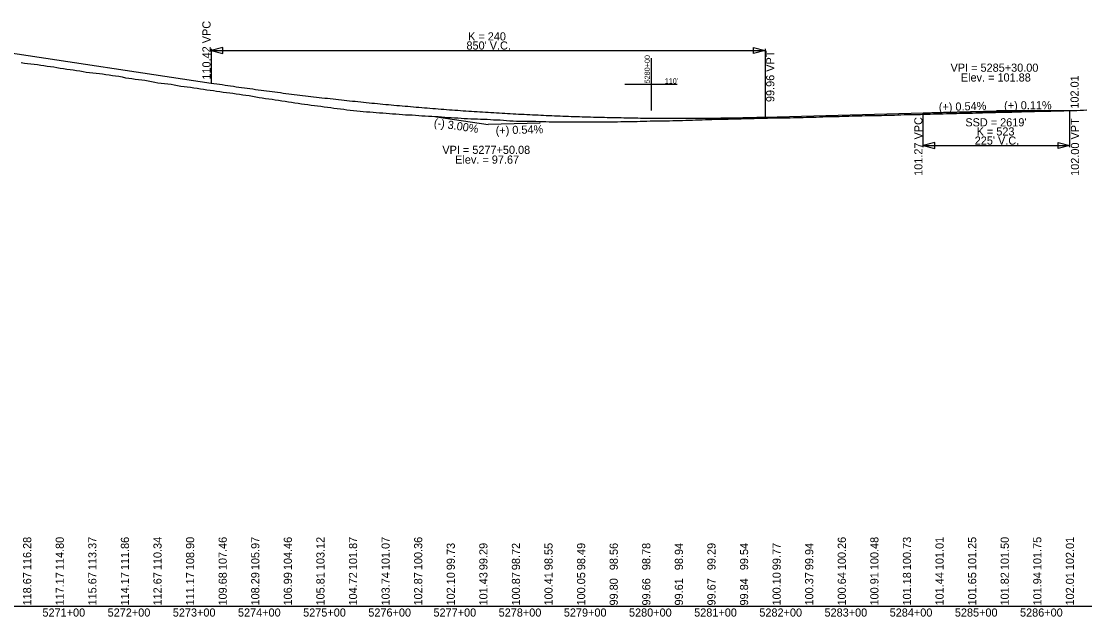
# Model space of a CAD drawing. Extents: x 2147288 to 2220488, y 740833 to 759333.
# Drawn here: x 2159415 to 2161047, y 742067 to 742980 of the extents above; entities that cross this region are included whole.
import ezdxf

# ---------------------------------------------------------------- set-up
doc = ezdxf.new("R2010")
doc.units = 0
for name, color, linetype in [('RD_DDB_GradeTX', 7, 'Continuous'), ('RD_DDB_Profile_EX', 7, 'Continuous'), ('RD_DDB_Profile_Lbl', 7, 'Continuous'), ('RD_DDB_Profile_PR', 7, 'Continuous'), ('RD_DDB_StaTX', 7, 'Continuous'), ('RD_DDB_StripGrade', 7, 'Continuous'), ('RD_DDB_VCLbl', 7, 'Continuous'), ('RD_GPK_Profile_Cell', 7, 'Continuous')]:
    doc.layers.add(name, color=color, linetype=linetype)

msp = doc.modelspace()

# ---------------------------------------------------------------- linework, layer by layer
at = {"layer": 'RD_DDB_GradeTX'}
for p, q in [((2160052, 742833.6), (2160131.2, 742821.8)), ((2160831.1, 742840.7), (2160911.1, 742842.8)), ((2160991.1, 742843.3), (2160911.1, 742842.8)), ((2160211.1, 742823.9), (2160131.2, 742821.8))]:
    msp.add_line(p, q, dxfattribs=at)
at = {"layer": 'RD_DDB_Profile_EX'}
for points in [[(2159414.6, 742916.9), (2159419.6, 742916.2), (2159424.6, 742915.5), (2159429.6, 742915), (2159434.6, 742914.4), (2159439.6, 742913.7), (2159444.6, 742913), (2159449.6, 742912.2), (2159454.6, 742911.4), (2159459.6, 742911), (2159464.6, 742910.2), (2159469.6, 742909.4), (2159474.6, 742908.4), (2159479.6, 742907.6), (2159484.6, 742907), (2159489.6, 742906.3), (2159494.6, 742905.5), (2159499.6, 742904.7), (2159504.6, 742904), (2159509.6, 742903.1), (2159514.6, 742902.1), (2159519.6, 742901.6), (2159524.6, 742901.1), (2159529.6, 742900.5), (2159534.6, 742899.9)], [(2159534.6, 742899.9), (2159539.6, 742899.4), (2159544.6, 742898.7), (2159549.6, 742897.9), (2159554.6, 742897.1), (2159559.6, 742896.6), (2159564.6, 742895.8), (2159569.6, 742894.8), (2159574.6, 742893.7), (2159579.6, 742892.9), (2159584.6, 742892.2), (2159589.6, 742891.5), (2159594.6, 742890.9), (2159599.6, 742890.6), (2159604.6, 742889.9), (2159609.6, 742889), (2159614.6, 742888), (2159619.6, 742887), (2159624.6, 742885.9), (2159629.6, 742885.3), (2159634.6, 742884.8), (2159639.6, 742884.2), (2159644.6, 742883.5), (2159649.6, 742882.7), (2159654.6, 742881.8), (2159659.6, 742880.8), (2159664.6, 742880.4), (2159669.6, 742879.9), (2159674.6, 742879.1), (2159679.6, 742878.1), (2159684.6, 742877.4), (2159689.6, 742876.7), (2159694.6, 742876), (2159699.6, 742875.3), (2159704.6, 742874.6), (2159709.6, 742873.8), (2159714.6, 742873.2), (2159719.6, 742872.5), (2159724.6, 742871.5), (2159729.6, 742870.9), (2159734.6, 742870.4), (2159739.6, 742869.8), (2159744.6, 742869), (2159749.6, 742868.2), (2159754.6, 742867.4), (2159759.6, 742867), (2159764.6, 742866.2), (2159769.6, 742865.2), (2159774.6, 742864.3), (2159779.6, 742863.5), (2159784.6, 742862.7), (2159789.6, 742861.9), (2159794.6, 742861.2), (2159799.6, 742860.5), (2159804.6, 742859.9), (2159809.6, 742859.1), (2159814.6, 742858.3), (2159819.6, 742857.5), (2159824.6, 742856.7), (2159829.6, 742856), (2159834.6, 742855.2), (2159839.6, 742854.5), (2159844.6, 742853.8), (2159849.6, 742853.1), (2159854.6, 742852.4), (2159859.6, 742851.7), (2159864.6, 742851.1), (2159869.6, 742850.6), (2159874.6, 742850), (2159879.6, 742849.2), (2159884.6, 742848.5), (2159889.6, 742847.8), (2159894.6, 742847.1), (2159899.6, 742846.5), (2159904.6, 742845.8), (2159909.6, 742845.2), (2159914.6, 742844.6), (2159919.6, 742844.1), (2159924.6, 742843.5), (2159929.6, 742842.9), (2159934.6, 742842.4), (2159939.6, 742841.9), (2159944.6, 742841.4), (2159949.6, 742841.1), (2159954.6, 742840.8), (2159959.6, 742840.4), (2159964.6, 742840), (2159969.6, 742839.6), (2159974.6, 742839.3), (2159979.6, 742838.9), (2159984.6, 742838.4), (2159989.6, 742838.1), (2159994.6, 742837.7), (2159999.6, 742837.2), (2160004.6, 742836.9), (2160009.6, 742836.7), (2160014.6, 742836.5), (2160019.6, 742836.1), (2160024.6, 742835.7), (2160029.6, 742835.4), (2160034.6, 742835)], [(2160534.6, 742831.2), (2160539.6, 742831.3), (2160544.6, 742831.4), (2160549.6, 742831.5), (2160554.6, 742831.6), (2160559.6, 742831.7), (2160564.6, 742831.9), (2160569.6, 742832.1), (2160574.6, 742832.2), (2160579.6, 742832.3), (2160584.6, 742832.3), (2160589.6, 742832.3), (2160594.6, 742832.3), (2160599.6, 742832.5), (2160604.6, 742832.6), (2160609.6, 742832.7), (2160614.6, 742832.8), (2160619.6, 742832.9), (2160624.6, 742833), (2160629.6, 742833.1), (2160634.6, 742833.2), (2160639.6, 742833.4), (2160644.6, 742833.7), (2160649.6, 742834), (2160654.6, 742834.1), (2160659.6, 742834.2), (2160664.6, 742834.4), (2160669.6, 742834.4), (2160674.6, 742834.5), (2160679.6, 742834.8), (2160684.6, 742834.7), (2160689.6, 742835), (2160694.6, 742835.2), (2160699.6, 742835.3), (2160704.6, 742835.4), (2160709.6, 742835.5), (2160714.6, 742835.5), (2160719.6, 742835.7), (2160724.6, 742835.7), (2160729.6, 742835.8), (2160734.6, 742835.9), (2160739.6, 742836), (2160744.6, 742836.1), (2160749.6, 742836.3), (2160754.6, 742836.3), (2160759.6, 742836.5), (2160764.6, 742836.8), (2160769.6, 742837), (2160774.6, 742837.1), (2160779.6, 742837.1), (2160784.6, 742837.1), (2160789.6, 742837.2), (2160794.6, 742837.3), (2160799.6, 742837.5), (2160804.6, 742837.7), (2160809.6, 742837.8), (2160814.6, 742838), (2160819.6, 742838.1), (2160824.6, 742838.3), (2160829.6, 742838.5), (2160834.6, 742838.6), (2160839.6, 742838.7), (2160844.6, 742838.8), (2160849.6, 742839), (2160854.6, 742839.2), (2160859.6, 742839.4), (2160864.6, 742839.5), (2160869.6, 742839.5), (2160874.6, 742839.5), (2160879.6, 742839.6), (2160884.6, 742839.8), (2160889.6, 742839.9), (2160894.6, 742840.1), (2160899.6, 742840.2), (2160904.6, 742840.3), (2160909.6, 742840.4), (2160914.6, 742840.6), (2160919.6, 742840.7), (2160924.6, 742840.8), (2160929.6, 742840.9), (2160934.6, 742841), (2160939.6, 742841.2), (2160944.6, 742841.3), (2160949.6, 742841.5), (2160954.6, 742841.6), (2160959.6, 742841.7), (2160964.6, 742841.8), (2160969.6, 742841.9), (2160974.6, 742842.1), (2160979.6, 742842.2), (2160984.6, 742842.3), (2160989.6, 742842.4), (2160994.6, 742842.5), (2160999.6, 742842.6), (2161004.6, 742842.7), (2161009.6, 742842.9), (2161014.6, 742843), (2161019.6, 742843.2), (2161024.6, 742843.3), (2161029.6, 742843.4), (2161034.6, 742843.6)], [(2161034.6, 742843.6), (2161039.6, 742843.7), (2161044.6, 742844), (2161049.6, 742844.2)], [(2160034.6, 742835), (2160039.6, 742834.9), (2160044.6, 742834.6), (2160049.6, 742834.2), (2160054.6, 742834), (2160059.6, 742833.6), (2160064.6, 742833.1), (2160069.6, 742832.8), (2160074.6, 742832.5), (2160079.6, 742832.2), (2160084.6, 742831.9), (2160089.6, 742831.7), (2160094.6, 742831.2), (2160099.6, 742830.9), (2160104.6, 742830.8), (2160109.6, 742830.7), (2160114.6, 742830.5), (2160119.6, 742830.3), (2160124.6, 742830.1), (2160129.6, 742829.9), (2160134.6, 742829.7), (2160139.6, 742829.3), (2160144.6, 742828.9), (2160149.6, 742828.9), (2160154.6, 742828.7), (2160159.6, 742828.1), (2160164.6, 742827.6), (2160169.6, 742827.3), (2160174.6, 742827.2), (2160179.6, 742827.1), (2160184.6, 742826.9), (2160189.6, 742826.8), (2160194.6, 742826.9), (2160199.6, 742826.9), (2160204.6, 742826.8), (2160209.6, 742826.6), (2160214.6, 742826.5), (2160219.6, 742826.4), (2160224.6, 742826.2), (2160229.6, 742826.2), (2160234.6, 742826.1), (2160239.6, 742826.1), (2160244.6, 742826), (2160249.6, 742826), (2160254.6, 742825.9), (2160259.6, 742825.9), (2160264.6, 742826), (2160269.6, 742826), (2160274.6, 742826), (2160279.6, 742825.9), (2160284.6, 742825.9), (2160289.6, 742825.9), (2160294.6, 742825.9), (2160299.6, 742826), (2160304.6, 742826.1), (2160309.6, 742826.1), (2160314.6, 742826.1), (2160319.6, 742826.2), (2160324.6, 742826.2), (2160329.6, 742826.2), (2160334.6, 742826.3), (2160339.6, 742826.3), (2160344.6, 742826.4), (2160349.6, 742826.5), (2160354.6, 742826.6), (2160359.6, 742826.7), (2160364.6, 742826.8), (2160369.6, 742827), (2160374.6, 742827.1), (2160379.6, 742827.3), (2160384.6, 742827.4), (2160389.6, 742827.5), (2160394.6, 742827.5), (2160399.6, 742827.6), (2160404.6, 742827.3), (2160409.6, 742827.7), (2160414.6, 742827.8), (2160419.6, 742827.9), (2160424.6, 742828), (2160429.6, 742828.1), (2160434.6, 742828.3), (2160439.6, 742828.5), (2160444.6, 742828.6), (2160449.6, 742828.8), (2160454.6, 742829), (2160459.6, 742829.2), (2160464.6, 742829.4), (2160469.6, 742829.6), (2160474.6, 742829.7), (2160479.6, 742829.9), (2160484.6, 742829.9), (2160489.6, 742830.1), (2160494.6, 742830.2), (2160499.6, 742830.3), (2160504.6, 742830.5), (2160509.6, 742830.6), (2160514.6, 742830.8), (2160519.6, 742830.8), (2160524.6, 742831), (2160529.6, 742831.1), (2160534.6, 742831.2)]]:
    msp.add_lwpolyline(points, dxfattribs=at)
at = {"layer": 'RD_DDB_Profile_PR'}
for p, q in [((2159381.1, 742934.3), (2159706.2, 742885.5)), ((2161023.6, 742843.4), (2161031.1, 742843.5)), ((2160556.2, 742833.2), (2160798.6, 742839.8))]:
    msp.add_line(p, q, dxfattribs=at)
for points in [[(2159706.2, 742885.5), (2159723.2, 742883), (2159740.2, 742880.5), (2159757.2, 742878.1), (2159774.2, 742875.8), (2159791.2, 742873.5), (2159808.2, 742871.3), (2159825.2, 742869.1), (2159842.2, 742867), (2159859.2, 742865), (2159876.2, 742863), (2159893.2, 742861.1), (2159910.2, 742859.2), (2159927.2, 742857.5), (2159944.2, 742855.7), (2159961.2, 742854), (2159978.2, 742852.4), (2159995.2, 742850.9), (2160012.2, 742849.4), (2160029.2, 742847.9), (2160046.2, 742846.6), (2160063.2, 742845.2), (2160080.2, 742844), (2160097.2, 742842.8), (2160114.2, 742841.6), (2160131.2, 742840.6), (2160148.2, 742839.6), (2160165.2, 742838.6), (2160182.2, 742837.7), (2160199.2, 742836.9), (2160216.2, 742836.1), (2160233.2, 742835.4), (2160250.2, 742834.7), (2160267.2, 742834.1), (2160284.2, 742833.6), (2160301.2, 742833.1), (2160318.2, 742832.7), (2160335.2, 742832.4), (2160352.2, 742832.1), (2160369.2, 742831.8), (2160386.2, 742831.7), (2160403.2, 742831.5), (2160420.2, 742831.5), (2160437.2, 742831.5), (2160454.2, 742831.6), (2160471.2, 742831.7), (2160488.2, 742831.9), (2160505.2, 742832.1), (2160522.2, 742832.4), (2160539.2, 742832.8), (2160556.2, 742833.2)], [(2160798.6, 742839.8), (2160803.1, 742839.9), (2160807.6, 742840), (2160812.1, 742840.1), (2160816.6, 742840.3), (2160821.1, 742840.4), (2160825.6, 742840.5), (2160830.1, 742840.6), (2160834.6, 742840.7), (2160839.1, 742840.8), (2160843.6, 742840.9), (2160848.1, 742841), (2160852.6, 742841.1), (2160857.1, 742841.2), (2160861.6, 742841.3), (2160866.1, 742841.4), (2160870.6, 742841.5), (2160875.1, 742841.6), (2160879.6, 742841.7), (2160884.1, 742841.7), (2160888.6, 742841.8), (2160893.1, 742841.9), (2160897.6, 742842), (2160902.1, 742842.1), (2160906.6, 742842.1), (2160911.1, 742842.2), (2160915.6, 742842.3), (2160920.1, 742842.4), (2160924.6, 742842.4), (2160929.1, 742842.5), (2160933.6, 742842.6), (2160938.1, 742842.6), (2160942.6, 742842.7), (2160947.1, 742842.7), (2160951.6, 742842.8), (2160956.1, 742842.9), (2160960.6, 742842.9), (2160965.1, 742843), (2160969.6, 742843), (2160974.1, 742843.1), (2160978.6, 742843.1), (2160983.1, 742843.1), (2160987.6, 742843.2), (2160992.1, 742843.2), (2160996.6, 742843.3), (2161001.1, 742843.3), (2161005.6, 742843.3), (2161010.1, 742843.4), (2161014.6, 742843.4), (2161019.1, 742843.4), (2161023.6, 742843.4)]]:
    msp.add_spline(points, degree=3, dxfattribs=at)
at = {"layer": 'RD_DDB_VCLbl'}
for p, q in [((2159706.2, 742938), (2159706.2, 742885.5)), ((2159706.2, 742935.5), (2160556.2, 742935.5)), ((2160556.2, 742938), (2160556.2, 742833.2)), ((2161023.6, 742787.3), (2161023.6, 742843.4)), ((2160798.6, 742787.3), (2160798.6, 742839.8)), ((2160798.6, 742789.8), (2161023.6, 742789.8))]:
    msp.add_line(p, q, dxfattribs=at)
for points in [[(2159724.2, 742940), (2159706.2, 742935.5), (2159724.2, 742931)], [(2160538.2, 742940), (2160556.2, 742935.5), (2160538.2, 742931)], [(2160816.6, 742794.3), (2160798.6, 742789.8), (2160816.6, 742785.3)], [(2161005.6, 742794.3), (2161023.6, 742789.8), (2161005.6, 742785.3)]]:
    msp.add_lwpolyline(points, close=True, dxfattribs=at)
at = {"layer": 'RD_GPK_Profile_Cell'}
for p, q in [((2160381.1, 742923.4), (2160381.1, 742843.4)), ((2160421.1, 742883.4), (2160341.1, 742883.4)), ((2148888.3, 742083.4), (2165888.3, 742083.4))]:
    msp.add_line(p, q, dxfattribs=at)

# ---------------------------------------------------------------- texts
at = {"layer": 'RD_DDB_GradeTX'}
for s, rotation, p in [('(+) 0.54%', 1.5466, (2160822.8, 742842.4)), ('(+) 0.11%', 0.3139, (2160922.9, 742844.9)), ('(-) 3.00%', 351.4692, (2160047.3, 742818.9)), ('(+) 0.54%', 1.5466, (2160142.9, 742806.6))]:
    msp.add_text(s, height=12.5, rotation=rotation, dxfattribs=at).set_placement(p)
at = {"layer": 'RD_DDB_Profile_Lbl'}
for s, p in [('VPI = 5285+30.00', (2160840.7, 742902.8)), ('Elev. = 101.88', (2160856.5, 742887.8)), ('VPI = 5277+50.08', (2160060.9, 742776.8)), ('Elev. = 97.67', (2160080.6, 742761.8))]:
    msp.add_text(s, height=12.5, dxfattribs=at).set_placement(p)
msp.add_text('102.01', height=12.5, rotation=90, dxfattribs=at).set_placement((2161037.3, 742846.2))
at = {"layer": 'RD_DDB_StaTX'}
for s, p in [('5271+00', (2159447.3, 742067.2)), ('5272+00', (2159547.3, 742067.2)), ('5273+00', (2159647.3, 742067.2)), ('5274+00', (2159747.3, 742067.2)), ('5275+00', (2159847.3, 742067.2)), ('5276+00', (2159947.3, 742067.2)), ('5277+00', (2160047.3, 742067.2)), ('5278+00', (2160147.3, 742067.2)), ('5279+00', (2160247.3, 742067.2)), ('5280+00', (2160347.3, 742067.2)), ('5281+00', (2160447.3, 742067.2)), ('5282+00', (2160547.3, 742067.2)), ('5283+00', (2160647.3, 742067.2)), ('5284+00', (2160747.3, 742067.2)), ('5285+00', (2160847.3, 742067.2)), ('5286+00', (2160947.3, 742067.2))]:
    msp.add_text(s, height=12.5, dxfattribs=at).set_placement(p)
at = {"layer": 'RD_DDB_StripGrade'}
for s, p in [('110.42 VPC', (2159705.2, 742890.7)), ('99.96 VPT', (2160570.3, 742856.3)), ('101.27 VPC', (2160797.6, 742743.1)), ('102.00 VPT', (2161037.9, 742743.1)), ('116.28', (2159430.1, 742138.4)), ('114.80', (2159480.1, 742138.4)), ('113.37', (2159530.1, 742138.4)), ('111.86', (2159580.1, 742138.4)), ('110.34', (2159630.1, 742138.4)), ('108.90', (2159680.1, 742138.4)), ('107.46', (2159730.1, 742138.4)), ('105.97', (2159780.1, 742138.4)), ('104.46', (2159830.1, 742138.4)), ('103.12', (2159880.1, 742138.4)), ('101.87', (2159930.1, 742138.4)), ('101.07', (2159980.1, 742138.4)), ('100.36', (2160030.1, 742138.4)), ('99.73', (2160080.1, 742138.4)), ('99.29', (2160130.1, 742138.4)), ('98.72', (2160180.1, 742138.4)), ('98.55', (2160230.1, 742138.4)), ('98.49', (2160280.1, 742138.4)), ('98.56', (2160330.1, 742138.4)), ('98.78', (2160380.1, 742138.4)), ('98.94', (2160430.1, 742138.4)), ('99.29', (2160480.1, 742138.4)), ('99.54', (2160530.1, 742138.4)), ('99.77', (2160580.1, 742138.4)), ('99.94', (2160630.1, 742138.4)), ('100.26', (2160680.1, 742138.4)), ('100.48', (2160730.1, 742138.4)), ('100.73', (2160780.1, 742138.4)), ('101.01', (2160830.1, 742138.4)), ('101.25', (2160880.1, 742138.4)), ('101.50', (2160930.1, 742138.4)), ('101.75', (2160980.1, 742138.4)), ('102.01', (2161030.1, 742138.4)), ('118.67', (2159430.1, 742084.2)), ('117.17', (2159480.1, 742084.2)), ('115.67', (2159530.1, 742084.2)), ('114.17', (2159580.1, 742084.2)), ('112.67', (2159630.1, 742084.2)), ('111.17', (2159680.1, 742084.2)), ('109.68', (2159730.1, 742084.2)), ('108.29', (2159780.1, 742084.2)), ('106.99', (2159830.1, 742084.2)), ('105.81', (2159880.1, 742084.2)), ('104.72', (2159930.1, 742084.2)), ('103.74', (2159980.1, 742084.2)), ('102.87', (2160030.1, 742084.2)), ('102.10', (2160080.1, 742084.2)), ('101.43', (2160130.1, 742084.2)), ('100.87', (2160180.1, 742084.2)), ('100.41', (2160230.1, 742084.2)), ('100.05', (2160280.1, 742084.2)), ('99.84', (2160530.1, 742084.2)), ('100.10', (2160580.1, 742084.2)), ('100.37', (2160630.1, 742084.2)), ('100.64', (2160680.1, 742084.2)), ('100.91', (2160730.1, 742084.2)), ('101.18', (2160780.1, 742084.2)), ('101.44', (2160830.1, 742084.2)), ('101.65', (2160880.1, 742084.2)), ('101.82', (2160930.1, 742084.2)), ('101.94', (2160980.1, 742084.2)), ('102.01', (2161030.1, 742084.2)), ('99.80', (2160330.1, 742084.2)), ('99.66', (2160380.1, 742084.2)), ('99.61', (2160430.1, 742084.2)), ('99.67', (2160480.1, 742084.2))]:
    msp.add_text(s, height=12.5, rotation=90, dxfattribs=at).set_placement(p)
at = {"layer": 'RD_DDB_VCLbl'}
for s, p in [('K = 240', (2160100.4, 742950.8)), ("850' V.C.", (2160097.9, 742936.8)), ("SSD = 2619'", (2160863.4, 742819)), ('K = 523', (2160880.7, 742805)), ("225' V.C.", (2160877.8, 742791))]:
    msp.add_text(s, height=12.5, dxfattribs=at).set_placement(p)
at = {"layer": 'RD_GPK_Profile_Cell'}
msp.add_text('5280+00', height=8, rotation=90, dxfattribs=at).set_placement((2160379.3, 742885))
msp.add_text("110'", height=8, dxfattribs=at).set_placement((2160402.2, 742884.6))

doc.saveas('drawing.dxf')
